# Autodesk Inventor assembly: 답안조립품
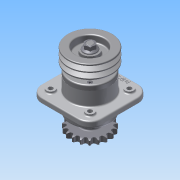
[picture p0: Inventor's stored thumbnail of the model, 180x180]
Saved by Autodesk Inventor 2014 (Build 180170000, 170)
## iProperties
Created: 2015-09
Part Number: 답안조립품
Document SubType Name: Assembly
Designer: study
Author: study
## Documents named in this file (11)
- C:\Users\study\Desktop\450909V1019\답안조립품.iam
- C:\Users\study\Desktop\450909V1019\1-본체.ipt
- C:\Users\study\Desktop\450909V1019\6-베어링 6206.ipt
- C:\Users\study\Desktop\450909V1019\3-축.ipt
- C:\Users\study\Desktop\450909V1019\2-커버.ipt
- C:\Users\study\Desktop\450909V1019\8-오일실 30x42.ipt
- C:\Users\study\Desktop\450909V1019\11-키 6x6.ipt
- C:\Users\study\Desktop\450909V1019\10-M6.ipt
- C:\Users\study\Desktop\450909V1019\4-V벨트풀리.ipt
- C:\Users\study\Desktop\450909V1019\9-M16-너트.ipt
- C:\Users\study\Desktop\450909V1019\5-체인 스프로킷.ipt
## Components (22 placed, 10 different names)
1. 1-본체:1
2. 6-베어링 6206:1
3. 6-베어링 6206:2
4. 3-축:1 — 각도:1, 각도:2
5. 2-커버:1
6. 2-커버:2
7. 8-8-오일실 30x42:1
8. 8-8-오일실 30x42:2
9. 11-키 6x6:1 — 각도:2, 각도:4
10. 11-키 6x6:2 — 각도:1, 각도:3
11. 4-V벨트풀리:1 — 각도:3
12. 9-M16 너트:1
13. 5-체인 스프로킷:1 — 각도:4
14. 9-M16 너트:2
15. 10-M6:2
16. 10-M6:3
17. 10-M6:4
18. 10-M6:5
19. 10-M6:1
20. 10-M6:6
21. 10-M6:7
22. 10-M6:8
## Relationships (4: Angle 4)
- 각도:1 [Angle]: 3-축:1 ↔ 11-키 6x6:2
- 각도:2 [Angle]: 3-축:1 ↔ 11-키 6x6:1
- 각도:3 [Angle]: 11-키 6x6:2 ↔ 4-V벨트풀리:1
- 각도:4 [Angle]: 11-키 6x6:1 ↔ 5-체인 스프로킷:1
